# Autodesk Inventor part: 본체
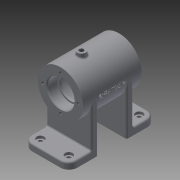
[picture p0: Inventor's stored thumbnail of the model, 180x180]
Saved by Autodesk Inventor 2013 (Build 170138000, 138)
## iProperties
Created: 2017-02
Part Number: 본체
Material: 일반
Document SubType Name: Modeling
Designer: Administrator
Density: 1 g/cm^3
Author: Administrator
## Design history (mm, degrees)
sketch "스케치1"
  geometry: C1 r 27 at (0, 0); 1 further point
  constraints: 1 centre point, 1 coincident
  dimensions: "d0" = 54 diameter of C1
extrude "돌출1" new body sketch "스케치1" stored distance "d2" = 70; taper "d3" = 0 deg
sketch "스케치2"
  geometry: L1 (-35, 27)-(-35, -27) reference; L2 (35, -27)-(35, 27) reference; L3 (-35, 0)-(35, 0); L4 (-35, 0)-(-23, 0); L5 (-23, 0)-(-23, 16); L6 (-23, 16)-(-35, 16); L7 (-35, 16)-(-35, 0); L8 (-23, 0)-(-20, 0); L9 (-20, 0)-(-20, 14); L10 (-20, 14)-(-23, 14); L11 (-23, 14)-(-23, 0); L12 (-20, 0)-(20, 0); L13 (20, 0)-(20, 22); L14 (20, 22)-(-20, 22); L15 (-20, 22)-(-20, 0); L16 (0, 0)-(0, -10.976); L17 (20, 0)-(20, 14); L18 (23, 0)-(20, 0); L19 (20, 14)-(23, 14); L20 (23, 0)-(23, 16); L21 (23, 14)-(23, 0); L22 (35, 0)-(23, 0); L23 (35, 16)-(35, 0); L24 (23, 16)-(35, 16)
  constraints: 44 end point, 7 parallel, 5 symmetric about line, 3 horizontal, 3 perpendicular, 2 midpoint
  dimensions: "d4" = 12 distance of L5.end L6.end; "d6" = 3 distance of L9.end L10.end; "d7" = 40 distance of L13.end L14.end; "d8" = 32 diameter of L6 L4; "d9" = 28 diameter of L10 L3; "d10" = 44 diameter of L14 L3
revolve "회전1" sketch "스케치2" stored, may be unused: angle "d11" = 90 deg
node "작업 평면1"
sketch "스케치3"
  geometry: L1 (-27, -35)-(27, -35) reference; L2 (0, -35)-(0, -10); C1 r 5 at (0, -10); 1 further point
  constraints: 2 end point, 1 centre point, 1 coincident, 1 midpoint, 1 perpendicular
  dimensions: "d13" = 25 distance of L2.start L2.end; "d14" = 10 diameter of C1
extrude "돌출2" join sketch "스케치3" stored distance "d15" = 70; taper "d16" = 0 deg
hole "구멍1" diameter "d19" = 5.188; stored, may be unused: countersink angle "d23" = 90 deg, drill point angle "d25" = 118 deg; dims "d20" = 6, "d21" = 4, "d22" = 2, "d24" = 8, "d26" = 10, "d27" = 10
sketch "스케치4"
  geometry: L1 (0, 0)-(0, 21); C1 r 27 at (0, 0) reference; 1 further point
  constraints: 2 end point, 1 coincident, 1 vertical
  dimensions: "d28" = 21 distance of L1.start L1.end
hole "구멍2" sketch "스케치4" at (0, 21) diameter "d29" = 3.242; stored, may be unused: countersink angle "d33" = 90 deg, drill point angle "d35" = 118 deg; dims "d30" = 8, "d31" = 4, "d32" = 2, "d34" = 10
fillet "모깎기1" dims "d39" = 0.3, "d40" = 2
node "작업 평면3"
sketch "스케치5"
  geometry: L1 (-27, -52)-(27, -52); L2 (27, -52)-(27, -60); L3 (27, -60)-(-27, -60); L4 (-27, -60)-(-27, -52); L5 (0, -52)-(0, -60); 2 further points
  constraints: 10 end point, 3 midpoint, 2 parallel, 2 perpendicular, 1 horizontal, 1 vertical alignment
  dimensions: "d43" = 54 distance of L2.end L3.end; "d46" = 8 distance of L1.end L2.end; "d47" = 60 distance from line of L3 point (0, 0)
extrude "돌출3" join sketch "스케치5" distance "d48" = 35; taper "d49" = 0 deg
sketch "스케치6"
  geometry: L1 (54, 0)-(54, -35) reference; L2 (0, 0)-(54, 0); L3 (54, 0)-(54, -8); L4 (54, -8)-(0, -8); L5 (0, -8)-(0, 0); 1 further point
  constraints: 8 end point, 2 parallel, 1 horizontal, 1 perpendicular, 1 point on line
  dimensions: "d50" = 8 distance of L2.end L3.end
extrude "돌출4" join sketch "스케치6" stored distance "d52" = 35; taper "d53" = 0 deg
fillet "모깎기2" dims "d54" = 10
hole "구멍3" diameter "d57" = 5; stored, may be unused: countersink angle "d61" = 90 deg, drill point angle "d63" = 118 deg; dims "d55" = 10, "d56" = 10, "d58" = 8, "d59" = 9, "d60" = 3, "d62" = 10
fillet "모깎기3" dims "d67" = 2
fillet "모깎기4" dims "d68" = 2
sketch "스케치7"
  geometry: L1 (0, 0)-(16.339, -25.16); L2 (0, 0)-(0, -13.074)
  constraints: 4 end point, 1 vertical
  dimensions: "d69" = 33 deg angle of L1 L2; "d70" = 30 distance of L1.start L1.end
node "작업 평면4"
sketch "스케치8"
  geometry: C1 r 6 at (0, 0); 2 further points
  constraints: 1 centre point, 1 coincident
  dimensions: "d71" = 12 diameter of C1
extrude "돌출5" join sketch "스케치8" stored distance "d72" = 35; taper "d73" = 0 deg
hole "구멍4" diameter "d76" = 5.188; stored, may be unused: countersink angle "d80" = 90 deg, drill point angle "d82" = 118 deg; dims "d74" = 10, "d75" = 10, "d77" = 8, "d78" = 9, "d79" = 3, "d81" = 10
node "작업 평면5"
sketch "스케치9"
  geometry: L1 (0, 5.847)-(0, -5.847); L2 (-14.782, 0)-(14.782, 0); L3 (-14.782, 5.847)-(14.782, 5.847); L4 (14.782, 5.847)-(14.782, -5.847); L5 (14.782, -5.847)-(-14.782, -5.847); L6 (-14.782, -5.847)-(-14.782, 5.847); 2 further points
  constraints: 4 end point, 1 coincident, 1 midpoint, 2 other
feature "엠보싱1" sketch "스케치9" dims "d4" = 12, "d6" = 3, "d7" = 40, "d8" = 32, "d9" = 28, "d10" = 44, "d83" = 0.5, "d84" = 0
fillet "모깎기5" dims "d85" = 2
chamfer "모따기1" distance "d86" = 1; stored, may be unused: second distance "d87" = 2, angle "d88" = 45 deg
node "솔리드1"
pattern_circular "원형 패턴1" dims angle "d37" = 360 deg
mirror "대칭1"
pattern_linear "직사각형 패턴1" dims "d66" = 34
mirror "대칭2"
other parameters: "d12" = 32, "d42" = -17
